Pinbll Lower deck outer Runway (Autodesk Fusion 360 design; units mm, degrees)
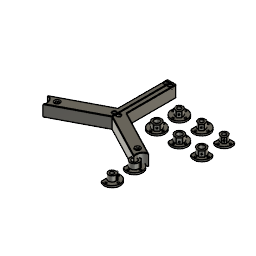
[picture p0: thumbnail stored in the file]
sketch "Sketch1" plane through (0, 0, 0) normal (0, 0, 1) x axis (1, 0, 0)
  line L1 (0, 135.8467) -> (0, 0)
  line L2 (-10, 22.6) -> (-10, 135.8467)
  line L3 (-10.1159, 22.8619) -> (-10, 22.6)
  line L4 (0, 0) -> (-101.4844, -52.9929)
  line L5 (-118.6545, -34.137) -> (-119.7629, -34.7158)
  line L6 (-10, 22.6) -> (-112.8997, -31.132)
  arc A1 centre (-5, 140) radius 6.5 clockwise from (0, 135.8467) to (-10, 135.8467)
  circle C1 centre (-5, 125) radius 4
  circle C2 centre (-5, 125) radius 2.25
  circle C3 centre (-5, 10) radius 4
  circle C4 centre (-5, 10) radius 2.25
  arc A2 centre (-114.7629, -46.0158) radius 15 clockwise from (-112.8997, -31.132) to (-101.4844, -52.9929)
  circle C5 centre (-89.6461, -32.7097) radius 4
  circle C6 centre (-89.6461, -32.7097) radius 2.25
  point P1 (0, 0)
  point P2 (0, 0)
  point P12 (0, 0)
  coincident P1 P2
  vertical L1
  concentric C1 C2
  concentric C3 C4
  coincident P1 P12
  collinear L5 L6
  concentric C5 C6
  dimension "d5" diameter A1 = 13
  dimension "d6" diameter C1 = 8
  dimension "d7" diameter C2 = 4.5
  dimension "d8" diameter C3 = 8
  dimension "d9" diameter C4 = 4.5
  dimension "d33" diameter C5 = 8
  dimension "d34" diameter C6 = 4.5
extrude "Extrude1" new body sketch "Sketch1" profile of L1 L2 L3 A1 C1 C2 C3 C4 along normal blind 25 bodies "Right Runway"
extrude "Extrude2" cut sketch "Sketch1" profile of C2 C4 along normal blind 30
extrude "Extrude3" cut sketch "Sketch1" profile of C1 C2 C3 C4 blind 10 from offset 20
fillet "Fillet1" radius 0.8
fillet "Fillet2" radius 2
fillet "Fillet3" radius 2
extrude "Extrude4" cut sketch "Sketch1" profile of C5 C6 blind 10 from offset 20
fillet "Fillet4" radius 2
mirror "Mirror1" mirrorStitchTolerance 0.1 bodies "Left Runway"
sketch "Inductive Sensor Bracket" plane through (0, 0, 0) normal (0, 0, 1) x axis (1, 0, 0)
  line L1 (57.5, 42.5) -> (50, 50)
  line L2 (61.0355, 46.0355) -> (57.5, 42.5)
  line L3 (57.5, 42.5) -> (53.9645, 38.9645)
  line L4 (59.6593, 47.4118) -> (61.0355, 46.0355)
  line L5 (52.5882, 40.3407) -> (53.9645, 38.9645)
  line L6 (111.0355, 46.0355) -> (107.5, 42.5)
  line L7 (109.6593, 47.4118) -> (111.0355, 46.0355)
  line L8 (107.5, 42.5) -> (100, 50)
  line L9 (107.5, 42.5) -> (103.9645, 38.9645)
  line L10 (102.5882, 40.3407) -> (103.9645, 38.9645)
  line L11 (90, 35.0334) -> (90, 64.9666)
  line L12 (157.5, 42.5) -> (153.9645, 38.9645)
  line L13 (152.5882, 40.3407) -> (153.9645, 38.9645)
  line L14 (157.5, 42.5) -> (150, 50)
  line L15 (140, 35.0334) -> (140, 50.0052)
  line L16 (159.6593, 47.4118) -> (161.0355, 46.0355)
  line L17 (161.0355, 46.0355) -> (157.5, 42.5)
  line L18 (164.9666, 60) -> (150, 60)
  line L19 (92, 83.8755) -> (92, 116.1245)
  line L20 (165.4577, 108) -> (150, 108)
  line L21 (142, 84.5423) -> (142, 100.0041)
  line L22 (156.4265, 93.5735) -> (153.6036, 90.7408)
  line L23 (152.0674, 92.2717) -> (153.6036, 90.7408)
  line L24 (57.7296, 97.9378) -> (59.3337, 96.3337)
  line L25 (106.5, 93.5) -> (100, 100)
  line L26 (157.7282, 97.9326) -> (159.2589, 96.3971)
  line L27 (156.4166, 93.5635) -> (150, 100)
  line L28 (107.7288, 97.9347) -> (109.3317, 96.3317)
  line L29 (50.8803, 92.0486) -> (52.9645, 89.9645)
  line L30 (56.5, 93.5) -> (50, 100)
  line L31 (56.5, 93.5) -> (52.9645, 89.9645)
  line L32 (59.3337, 96.3337) -> (56.5, 93.5)
  line L33 (100.8803, 92.0486) -> (102.9645, 89.9645)
  line L34 (109.3317, 96.3317) -> (106.5, 93.5)
  line L35 (106.5, 93.5) -> (102.9645, 89.9645)
  line L36 (159.2589, 96.3971) -> (156.4265, 93.5735)
  circle C1 centre (50, 50) radius 6.15
  circle C2 centre (50, 50) radius 18
  circle C3 centre (64, 50) radius 2.25
  circle C4 centre (36, 50) radius 2.25
  circle C5 centre (50, 64) radius 2.25
  circle C6 centre (50, 36) radius 2.25
  arc A1 centre (50, 50) radius 10 clockwise from (52.5882, 40.3407) to (59.6593, 47.4118)
  circle C7 centre (100, 36) radius 2.25
  circle C8 centre (114, 50) radius 2.25
  arc A2 centre (100, 50) radius 10 clockwise from (102.5882, 40.3407) to (109.6593, 47.4118)
  circle C9 centre (100, 50) radius 6.15
  circle C10 centre (100, 64) radius 2.25
  arc A3 centre (100, 50) radius 18 clockwise from (90, 64.9666) to (90, 35.0334)
  circle C11 centre (150, 36) radius 2.25
  arc A4 centre (150, 50) radius 10 clockwise from (152.5882, 40.3407) to (159.6593, 47.4118)
  circle C12 centre (164, 50) radius 2.25
  circle C13 centre (150, 50) radius 6.15
  arc A5 centre (150, 50) radius 18 clockwise from (164.9666, 60) to (140, 35.0334)
  circle C14 centre (100, 114) radius 2.25
  arc A6 centre (100, 100) radius 18 clockwise from (92, 116.1245) to (92, 83.8755)
  circle C15 centre (100, 86) radius 2.25
  circle C16 centre (114, 100) radius 2.25
  arc A7 centre (50, 100) radius 8 clockwise from (50.8803, 92.0486) to (57.7296, 97.9378)
  arc A8 centre (150, 100) radius 8 clockwise from (152.0674, 92.2717) to (157.7282, 97.9326)
  circle C17 centre (100, 100) radius 4.15
  circle C18 centre (164, 100) radius 2.25
  circle C19 centre (150, 100) radius 4.15
  circle C20 centre (36, 100) radius 2.25
  circle C21 centre (64, 100) radius 2.25
  circle C22 centre (50, 86) radius 2.25
  circle C23 centre (50, 100) radius 4.15
  arc A9 centre (150, 100) radius 17.4052 clockwise from (165.4577, 108) to (142, 84.5423)
  circle C24 centre (50, 114) radius 2.25
  circle C25 centre (150, 86) radius 2.25
  arc A10 centre (100, 100) radius 8 clockwise from (100.8803, 92.0486) to (107.7288, 97.9347)
  circle C26 centre (50, 100) radius 18
  point P4 (50, 50)
  point P9 (50, 50)
  point P18 (100, 50)
  point P21 (100, 50)
  point P34 (150, 50)
  point P43 (150, 50)
  point P45 (150, 60)
  point P46 (140, 50.0052)
  point P49 (50, 100)
  point P52 (50, 100)
  point P67 (100, 100)
  point P86 (100, 100)
  point P56 (150, 100)
  point P69 (150, 100)
  point P59 (150, 108)
  point P70 (142, 100.0041)
  point P91 (156.4166, 93.5635)
  concentric C2 A1
  coincident P4 P9
  perpendicular L1 L2
  perpendicular L2 L4
  perpendicular L3 L5
  concentric A2 A3
  coincident P18 P21
  perpendicular L6 L8
  perpendicular L6 L7
  perpendicular L9 L10
  vertical L11
  concentric A4 A5
  coincident P34 P43
  perpendicular L14 L17
  perpendicular L16 L17
  perpendicular L12 L13
  vertical L15
  perpendicular L15 L18
  coincident A4 P45
  coincident A4 P46
  concentric A7 C26
  coincident P49 P52
  perpendicular L30 L32
  perpendicular L24 L32
  perpendicular L29 L31
  concentric A6 A10
  coincident P67 P86
  perpendicular L25 L34
  perpendicular L28 L34
  perpendicular L33 L35
  vertical L19
  concentric A8 A9
  coincident P56 P69
  perpendicular L22 L23
  vertical L21
  perpendicular L20 L21
  coincident P59 A8
  coincident P70 A8
  perpendicular L26 L36
  coincident L22 P91
  dimension "d42" diameter C1 = 12.3
  dimension "d43" diameter C2 = 36
  dimension "d52" diameter A1 = 20
  dimension "d53" diameter C3 = 4.5
  dimension "d54" diameter C4 = 4.5
  dimension "d55" diameter C5 = 4.5
  dimension "d56" diameter C6 = 4.5
  dimension "d67" diameter C9 = 12.3
  dimension "d69" diameter A2 = 20
  dimension "d70" diameter C8 = 4.5
  dimension "d72" diameter C10 = 4.5
  dimension "d73" diameter C7 = 4.5
  dimension "d74" diameter C13 = 12.3
  dimension "d75" diameter A4 = 20
  dimension "d76" diameter C12 = 4.5
  dimension "d78" diameter C11 = 4.5
  dimension "d99" diameter C23 = 8.3
  dimension "d100" diameter C26 = 36
  dimension "d101" diameter A7 = 16
  dimension "d102" diameter C21 = 4.5
  dimension "d103" diameter C20 = 4.5
  dimension "d104" diameter C24 = 4.5
  dimension "d105" diameter C22 = 4.5
  dimension "d106" diameter C17 = 8.3
  dimension "d107" diameter A10 = 16
  dimension "d108" diameter C16 = 4.5
  dimension "d109" diameter C14 = 4.5
  dimension "d110" diameter C15 = 4.5
  dimension "d111" diameter C19 = 8.3
  dimension "d112" diameter A8 = 16
  dimension "d113" diameter C18 = 4.5
  dimension "d114" diameter C25 = 4.5
extrude "Extrude5" new body sketch "Inductive Sensor Bracket" profile of C1 C2 A1 C3 C4 C5 C6 L1 L2 L3 L4 L5 along normal blind 4 bodies "Sensor Bracket Full"
extrude "Extrude6" add sketch "Inductive Sensor Bracket" profile of C1 A1 L2 L3 L4 L5 along normal blind 16
sketch "Sketch3" plane through (7.5, -7.5, 0) normal (0.7071, -0.7071, 0) x axis (0.7071, 0.7071, 0)
  line L1 (75.7107, 4) -> (65.7107, 4)
  line L2 (75.7107, 16) -> (75.7107, 4)
  line L3 (65.7107, 16) -> (75.7107, 16)
  line L4 (65.7107, 4) -> (65.7107, 16)
  circle C1 centre (70.7841, 10.0881) radius 1.45
  dimension "d62" diameter C1 = 2.9
extrude "Extrude7" cut sketch "Sketch3" profile of C1 against normal blind 6
chamfer "Chamfer1" distance 0.2 distance 2
extrude "Extrude8" new body sketch "Inductive Sensor Bracket" profile of L6 L7 C7 L8 C8 A2 A3 L9 L10 C9 C10 L11 along normal blind 4 bodies "Sensor Bracket Half"
extrude "Extrude9" new body sketch "Inductive Sensor Bracket" profile of L12 C11 L13 A4 L14 C12 L15 C13 L16 L17 A5 L18 along normal blind 4 bodies "Sensor Bracket Quater"
extrude "Extrude10" add sketch "Inductive Sensor Bracket" profile of L6 L7 A2 L9 L10 C9 along normal blind 16
extrude "Extrude11" add sketch "Inductive Sensor Bracket" profile of L12 L13 A4 C13 L16 L17 along normal blind 16
sketch "Sketch4" plane through (32.5, -32.5, 0) normal (0.7071, -0.7071, 0) x axis (0.7071, 0.7071, 0)
  line L1 (111.066, 4) -> (101.066, 4)
  line L2 (111.066, 16) -> (111.066, 4)
  line L3 (101.066, 16) -> (111.066, 16)
  line L4 (101.066, 4) -> (101.066, 16)
  circle C1 centre (106.066, 8.2) radius 1.4
  dimension "d87" diameter C1 = 2.8
sketch "Sketch5" plane through (57.5, -57.5, 0) normal (0.7071, -0.7071, 0) x axis (0.7071, 0.7071, 0)
  line L1 (146.4214, 4) -> (136.4214, 4)
  line L2 (146.4214, 16) -> (146.4214, 4)
  line L3 (136.4214, 16) -> (146.4214, 16)
  line L4 (136.4214, 4) -> (136.4214, 16)
  circle C1 centre (141.4214, 10) radius 1.4
  dimension "d88" diameter C1 = 2.8
extrude "Extrude12" cut sketch "Sketch5" profile of C1 against normal blind 6
extrude "Extrude13" cut sketch "Sketch4" profile of C1 against normal blind 6
chamfer "Chamfer2" distance 0.35 distance 2
chamfer "Chamfer3" distance 0.35 distance 2
mirror "Mirror2" mirrorStitchTolerance 0.1 bodies "Sensor Bracket Half Mirrored"
extrude "Extrude14" new body sketch "Inductive Sensor Bracket" profile of A7 L24 C20 C21 C22 C23 L29 L30 L31 L32 C24 C26 along normal blind 4 bodies "Sensor Bracket 8mm Full"
extrude "Extrude15" new body sketch "Inductive Sensor Bracket" profile of L19 C14 A6 C15 C16 C17 L25 L28 L33 L34 L35 A10 along normal blind 4 bodies "Sensor Bracket 8mm Half"
extrude "Extrude16" new body sketch "Inductive Sensor Bracket" profile of L20 L21 L22 A8 L23 C18 C19 L26 L27 A9 C25 L36 along normal blind 4 bodies "Sensor Bracket 8mm Quarter"
extrude "Extrude17" add sketch "Inductive Sensor Bracket" profile of L22 A8 L23 C19 L26 L36 along normal blind 16
extrude "Extrude18" add sketch "Inductive Sensor Bracket" profile of C17 L28 L33 L34 L35 A10 along normal blind 16
extrude "Extrude19" add sketch "Inductive Sensor Bracket" profile of A7 L24 C23 L29 L31 L32 along normal blind 16
sketch "Sketch6" plane through (-18.5, 18.5, 0) normal (0.7071, -0.7071, 0) x axis (0.7071, 0.7071, 0)
  line L1 (110.0735, 4) -> (101.066, 4)
  line L2 (110.0735, 16) -> (110.0735, 4)
  line L3 (101.066, 16) -> (110.0735, 16)
  line L4 (101.066, 4) -> (101.066, 16)
  circle C1 centre (105.5698, 10) radius 1.4
  dimension "d127" diameter C1 = 2.8
sketch "Sketch7" plane through (6.5, -6.5, 0) normal (0.7071, -0.7071, 0) x axis (0.7071, 0.7071, 0)
  line L1 (145.426, 4) -> (136.4214, 4)
  line L2 (145.426, 16) -> (145.426, 4)
  line L3 (136.4214, 16) -> (145.426, 16)
  line L4 (136.4214, 4) -> (136.4214, 16)
  circle C1 centre (140.9237, 10) radius 1.4
  dimension "d128" diameter C1 = 2.8
sketch "Sketch8" plane through (31.1843, -31.2811, 0) normal (0.706, -0.7082, 0) x axis (0.7082, 0.706, 0)
  line L1 (180.8448, 4) -> (176.8454, 4)
  line L2 (180.8448, 16) -> (180.8448, 4)
  line L3 (176.8454, 16) -> (180.8448, 16)
  line L4 (176.8454, 4) -> (176.8454, 16)
  circle C1 centre (176.8454, 10) radius 1.4
  dimension "d129" diameter C1 = 2.8
extrude "Extrude20" cut sketch "Sketch8" profile of L4 C1 against normal blind 6 and along normal blind 0.1
chamfer "Chamfer4" distance 0.3 distance 2
extrude "Extrude21" cut sketch "Sketch7" profile of C1 against normal blind 6
chamfer "Chamfer5" distance 0.3 distance 2
extrude "Extrude22" cut sketch "Sketch6" profile of C1 against normal blind 6
chamfer "Chamfer6" distance 0.3 distance 2
mirror "Mirror3" mirrorStitchTolerance 0.1 bodies "Sensor Bracket 8mm Half Mirrored"
named bodies: "Right Runway", "Left Runway", "Sensor Bracket Full", "Sensor Bracket Half", "Sensor Bracket Quater", "Sensor Bracket Half Mirrored", "Sensor Bracket 8mm Full", "Sensor Bracket 8mm Half", "Sensor Bracket 8mm Quarter", "Sensor Bracket 8mm Half Mirrored"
